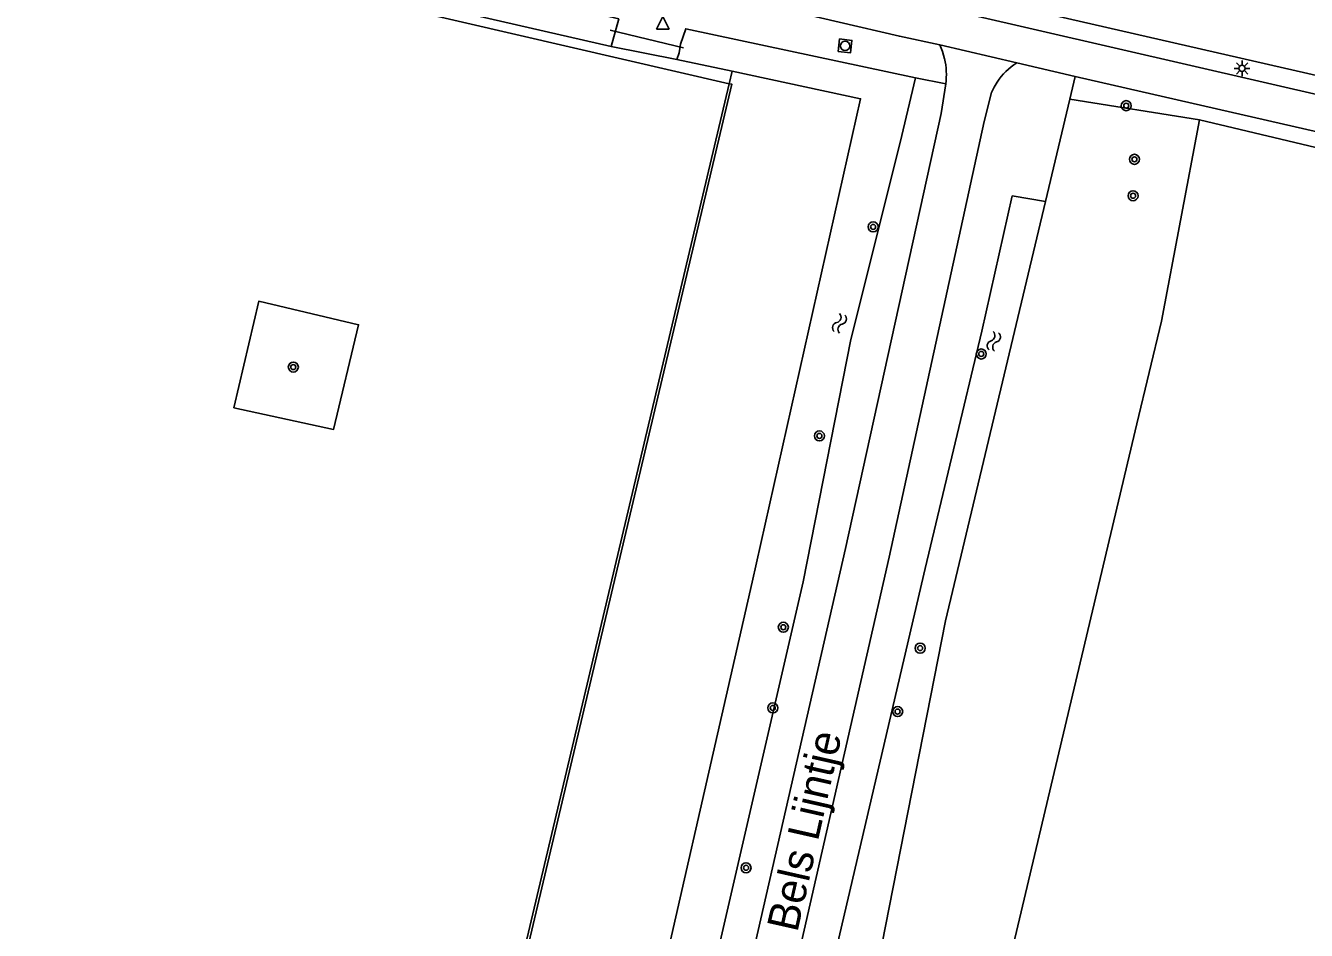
# Model space of a CAD drawing. Extents: x 128999 to 131010, y 395498 to 399007.
# Drawn here: x 129658.4 to 129760.3, y 396852.7 to 396924.7 of the extents above; entities that cross this region are included whole.
import ezdxf

# ---------------------------------------------------------------- set-up
doc = ezdxf.new("R2010")
doc.units = 0
for name, color, linetype in [('gg-afsc-draadraster', 7, 'Continuous'), ('gg-afsc-hekwerk', 7, 'Continuous'), ('gg-afsc-lijn draadraster', 7, 'Continuous'), ('gg-anno-openbare ruimte label', 7, 'Continuous'), ('gg-knt-bronhoudergrens', 7, 'Continuous'), ('gg-knt-verharding', 7, 'Continuous'), ('gg-kntw-bovenkant insteek waterloop', 7, 'Continuous'), ('gg-kwrk-duiker nz buis', 7, 'Continuous'), ('gt-grn-groengrens', 7, 'Continuous'), ('gt-symb-boom', 7, 'Continuous'), ('gt-symb-lichtmast', 7, 'Continuous'), ('gt-symb-rioolschacht', 7, 'Continuous'), ('gt-symb-waterafsluiter', 7, 'Continuous'), ('gt-symb-watersymbool', 7, 'Continuous'), ('gx-grn-maaiveld', 7, 'Continuous')]:
    doc.layers.add(name, color=color, linetype=linetype)

# ---------------------------------------------------------------- blocks, each defined once
blk = doc.blocks.new('gt0-BOOM')
at = {"layer": 'gt-symb-boom'}
for radius in [0.4, 0.2]:
    blk.add_circle((0, 0), radius, dxfattribs=at)
blk = doc.blocks.new('gt0-WA')
at = {"layer": 'gt-symb-watersymbool'}
for centre, start, end in [((-0.32, 0.02), 28.0725, 151.9275), ((0.43, 0.42), 208.0725, 331.9275), ((-0.32, -0.43), 28.0725, 151.9275), ((0.43, -0.03), 208.0725, 331.9275)]:
    blk.add_arc(centre, 0.425, start, end, dxfattribs=at)
blk = doc.blocks.new('gt0-RS')
at = {"layer": 'gt-symb-rioolschacht'}
blk.add_lwpolyline([(-0.5, -0.5), (0.5, -0.5), (0.5, 0.5), (-0.5, 0.5)], close=True, dxfattribs=at)
blk.add_circle((0, 0), 0.375, dxfattribs=at)
blk = doc.blocks.new('gt0-WAFSL')
at = {"layer": 'gt-symb-waterafsluiter'}
for p, q in [((-0.5, -0.33), (0, 0.67)), ((0, 0.67), (0.5, -0.33)), ((0.5, -0.33), (-0.5, -0.33))]:
    blk.add_line(p, q, dxfattribs=at)
blk = doc.blocks.new('gt0-LMAST')
at = {"layer": 'gt-symb-lichtmast'}
for p, q in [((-0.18, 0.17), (-0.45, 0.44)), ((-0.01, 0.25), (-0.01, 0.62)), ((0.17, 0.17), (0.44, 0.44)), ((-0.26, 0), (-0.63, 0)), ((-0.18, -0.18), (-0.45, -0.45)), ((-0.01, -0.25), (-0.01, -0.63)), ((0.44, -0.45), (0.17, -0.18)), ((0.24, 0), (0.62, 0))]:
    blk.add_line(p, q, dxfattribs=at)
blk.add_circle((-0.01, 0), 0.25, dxfattribs=at)

msp = doc.modelspace()

# ---------------------------------------------------------------- linework, layer by layer
at = {"layer": 'gg-afsc-draadraster'}
for p, q in [((129714.4, 396920.05), (129714.63, 396921.04)), ((129748.82, 396901.15), (129751.85, 396917.18))]:
    msp.add_line(p, q, dxfattribs=at)
for points in [[(129714.4, 396920.05), (129621.32, 396941.57), (129585.32, 396783.02)], [(129748.82, 396901.15), (129746.84, 396892.99), (129740.4, 396865.79), (129725.47, 396802.77), (129719.09, 396778.3)]]:
    msp.add_lwpolyline(points, dxfattribs=at)
at = {"layer": 'gg-afsc-hekwerk'}
msp.add_line((129781.67, 396910.05), (129751.85, 396917.18), dxfattribs=at)
msp.add_line((129781.67, 396910.05), (129751.85, 396917.18), dxfattribs=at)
at = {"layer": 'gg-afsc-lijn draadraster'}
for p, q in [((129714.4, 396920.05), (129714.63, 396921.04)), ((129748.82, 396901.15), (129751.85, 396917.18))]:
    msp.add_line(p, q, dxfattribs=at)
for points in [[(129677.15, 396763.34), (129677.29, 396763.45), (129692.34, 396826.84), (129714.4, 396920.05)], [(129748.82, 396901.15), (129746.84, 396892.99), (129740.4, 396865.79), (129725.47, 396802.77), (129719.09, 396778.3)]]:
    msp.add_lwpolyline(points, dxfattribs=at)
at = {"layer": 'gg-knt-bronhoudergrens'}
msp.add_lwpolyline([(129674.96, 396894.26), (129676.95, 396902.73), (129684.89, 396900.87), (129682.9, 396892.54), (129674.96, 396894.26)], dxfattribs=at)
at = {"layer": 'gg-knt-verharding'}
for p, q in [((129625.69, 396951.83), (129777.5, 396916.93)), ((129625.38, 396950.49), (129777.13, 396915.52)), ((129731.17, 396923.13), (129737.29, 396921.7)), ((129737.29, 396921.7), (129741.94, 396920.63)), ((129741.94, 396920.63), (129761.31, 396916.18))]:
    msp.add_line(p, q, dxfattribs=at)
for points in [[(129708.74, 396928.32), (129727.95, 396923.82), (129731.17, 396923.13)], [(129731.17, 396923.13), (129731.39, 396922.6), (129731.55, 396922.04)], [(129735.73, 396920.17), (129735.49, 396919.78), (129735.29, 396919.36), (129734.71, 396917.05), (129727.14, 396882.37), (129716.81, 396837.08), (129706.95, 396794.08), (129685.81, 396701.69), (129680.84, 396679.49), (129673.53, 396647.36), (129661.5, 396594.95), (129655, 396566.06), (129633.52, 396471), (129615.64, 396392.22), (129598.98, 396319.19), (129595.9, 396305.04), (129592.89, 396290.87), (129590.35, 396278.71), (129587.86, 396266.54), (129587.71, 396265.51)], [(129731.64, 396920.03), (129731.27, 396917.69), (129723.66, 396883.05), (129703.51, 396794.99), (129682.4, 396702.62), (129670.08, 396648.14), (129658.06, 396595.88), (129651.59, 396567.11), (129629.86, 396470.92), (129612.21, 396393.28), (129595.9, 396321.59)]]:
    msp.add_lwpolyline(points, dxfattribs=at)
for centre, radius, start, end in [((129726.24, 396920.81), 5.45, 351.794, 13.0515), ((129740.17, 396917.22), 5.33, 122.7265, 146.3449)]:
    msp.add_arc(centre, radius, start, end, dxfattribs=at)
at = {"layer": 'gg-kntw-bovenkant insteek waterloop'}
for p, q in [((129705, 396923), (129621.18, 396942.28)), ((129714.63, 396921.04), (129710.24, 396921.98)), ((129736.93, 396911.13), (129739.57, 396910.67))]:
    msp.add_line(p, q, dxfattribs=at)
for points in [[(129621.18, 396942.28), (129621.75, 396944.77), (129705.61, 396925.21), (129705, 396923)], [(129710.24, 396921.98), (129710.42, 396922.5), (129710.53, 396923.19), (129710.94, 396924.42), (129729.22, 396920.51)], [(129686.08, 396747.53), (129706.69, 396838.64), (129716.23, 396880.39), (129724.86, 396918.85), (129714.63, 396921.04)], [(129729.22, 396920.51), (129728, 396915.38), (129724.08, 396899.7), (129720.28, 396880.41), (129710.5, 396838), (129701.63, 396797.56), (129680.24, 396702.76), (129674.82, 396680.67), (129667.11, 396648.89), (129655.25, 396595.05), (129649.26, 396567.23), (129626.88, 396472.34), (129608.84, 396393.62), (129596.75, 396339.58), (129592.25, 396322.41), (129591.88, 396321.11)], [(129736.93, 396911.13), (129734.51, 396900.36), (129730, 396881.47), (129719.43, 396836.28), (129709.1, 396793.42), (129688.77, 396698.49), (129683.95, 396679.31), (129676.09, 396647.03)], [(129739.57, 396910.67), (129731.62, 396877.31), (129723.28, 396834.91), (129710.89, 396780.16)]]:
    msp.add_lwpolyline(points, dxfattribs=at)
at = {"layer": 'gg-kwrk-duiker nz buis'}
msp.add_line((129710.77, 396922.9), (129704.92, 396924.31), dxfattribs=at)
at = {"layer": 'gt-grn-groengrens'}
for p, q in [((129710.24, 396921.98), (129705, 396923)), ((129729.22, 396920.51), (129731.64, 396920.03)), ((129741.51, 396918.81), (129741.94, 396920.63)), ((129739.57, 396910.67), (129741.51, 396918.81)), ((129751.85, 396917.18), (129741.51, 396918.81))]:
    msp.add_line(p, q, dxfattribs=at)
at = {"layer": 'gx-grn-maaiveld'}
msp.add_lwpolyline([(129714.4, 396920.05), (129714.62, 396920), (129692.56, 396826.78), (129677.52, 396763.5), (129677.29, 396763.16), (129675.89, 396762.07), (129674.59, 396761.61), (129673.16, 396761.34), (129671.61, 396761.77), (129669.94, 396762.46)], dxfattribs=at)

# ---------------------------------------------------------------- block references
at = {"layer": 'gt-symb-boom'}
for p in [(129746.01, 396918.3), (129746.66, 396914.03), (129746.55, 396911.13), (129725.86, 396908.65), (129734.47, 396898.54), (129679.7, 396897.5), (129721.58, 396892.02), (129718.71, 396876.79), (129729.6, 396875.13), (129717.87, 396870.37), (129727.81, 396870.08), (129715.74, 396857.65)]:
    msp.add_blockref('gt0-BOOM', p, dxfattribs=at)
at = {"layer": 'gt-symb-lichtmast'}
msp.add_blockref('gt0-LMAST', (129755.24, 396921.27), dxfattribs=at)
at = {"layer": 'gt-symb-rioolschacht', "rotation": -6.890548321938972}
msp.add_blockref('gt0-RS', (129723.62, 396923.06), dxfattribs=at)
at = {"layer": 'gt-symb-waterafsluiter'}
msp.add_blockref('gt0-WAFSL', (129709.11, 396924.72), dxfattribs=at)
at = {"layer": 'gt-symb-watersymbool'}
for p, rotation in [((129723.16, 396900.93), 73.55871950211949), ((129735.45, 396899.49), 77.81315978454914)]:
    msp.add_blockref('gt0-WA', p, dxfattribs=dict(at, rotation=rotation))

# ---------------------------------------------------------------- texts
at = {"layer": 'gg-anno-openbare ruimte label'}
msp.add_text('Bels Lijntje', height=2.5, rotation=77.3, dxfattribs=at).set_placement((129719.82, 396852.45))

doc.saveas('drawing.dxf')
